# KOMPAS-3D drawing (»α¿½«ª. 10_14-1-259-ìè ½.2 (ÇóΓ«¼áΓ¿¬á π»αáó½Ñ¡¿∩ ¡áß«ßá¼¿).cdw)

Views: Вид 1
Referenced files in C:\Users\РЗА Елена\Desktop\: Библиотека РЗА.lfr|02 - Вторичные цепи|Контакты|Контакт 01, Библиотека РЗА.lfr, Библиотека РЗА.lfr|02 - Вторичные цепи|Клеммы, перемычки, соединения|01-Клемма
Referenced files in C:\Program Files\ASCON\KOMPAS-3D V10\Libs\: Библиотека РЗА.lfr
Referenced files in X:\Проекты\ПС 110 кВ Северные ЭС\5. ПС Опорная\2. Проект\04-РЗА\Рабочая документация\022-УА\: 1014-1-022-УА (Телеизмерения 110 кВ).cdw
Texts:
  РЗА Роман
  Текст на чертеже
  Размерные надписи
  Шероховатость
  Линия-выноска #1
  Линия-выноска #2
  Линия-выноска #3
  Отклонения формы и база
  Заголовок таблицы
  Ячейка таблицы
  Стрелка вида
  Обозначение изменения
  Фигурная скобка
  Номер узла
  Марка координационной оси
  VRCB
  Выносная надпись
  Обозначение узла
  Марка/позиционное обозначение с линией-выноской
  Марка/позиционное обозначение на линии
  Марка/позиционное обозначение без линии-выноски
  02 - Вторичные цепи|Контакты|Контакт 01
  02 - Вторичные цепи|Клеммы, перемычки, соединения|01-Клемма
  CONTINUOUS0
  Стили документа
  Без имени
  Additional DXF text style 0
  Лит-Масса-Масштаб
  Материал-Предприятие
  Normal
  Обычный
  Термин
  Список определений
  Адрес
  Цитаты
  Форматированный
  Courier New
  Z-конец формы
  Z-начало формы
  Title Specification
  Body Specification ( left align )
  Body Specificaton ( centered )
  Body Text
  цепи
  ссылки
  табл
  Подпись в квадратике
  Тексты. 3,2
  ЗОНА_привяз
  heading 1
  Знак Знак Знак Знак Знак Знак
  Verdana
  Body Text 3
  Title
  текст переноса
  ТекстШаг1
  Маркировка
  клеммы, контакты
  тексты табл
  ООббыыччнныыйй
  ТТееррммиинн
  ССппииссоокк ооппррееддееллеенниийй
  ААддрреесс
  ЦЦииттааттыы
  ФФооррммааттиирроовваанннныыйй
  Z-ккооннеецц ффооррммыы
  Z-ннааччааллоо ффооррммыы
  Simplex
  Txt
  MS Sans Serif
  heading 2
  AGOpus
  footer
  russ
  Аппараты
  подписи
  txt
  style2
  Definition Term
  Definition List
  Address
  Blockquote
  Preformatted
  z-Bottom of Form
  z-Top of Form
  TXT
  Абзац Знак
  Шрифт 2.5
  Заголовки
  Table Contents
  Table Heading
  Денис
  header
  HeliosLight
  Pa3
  Pa1
  heading 8
  heading 3
  heading 6
  heading 7
  heading 4
  heading 5
  heading 9
  ГОСТ_МНЕ
  ESK - Обозначение
  GOST 2.304 type A
  rustxt
  RUSTXT
  маркировка
  Состав чартежа
  ячейка табл.
  Tahoma
  Ссылки
  Пояснения
  Клеммник текст
  Текст 3,5
  .07 RGB_0_0_0 i0b0u0
  ISOCP
  CM12
  romans
  текст табл
  Body Text Indent 3
  Основной текст с отступом 3
  терминал
  Перечень элементов
  Поз.
  обозначение
  Кол.
  KSL1, KSL2
  Датчик реле-уровня жидкости
  см.п.п. 3
  Примечания:
  Разводка кабеля силовой и осветительной сети очистной установки включить в поставку
  завода-изготовителя.
  Сигнал "Вызов к шкафу автоматики управления насосами" включает:
  - аварийное отключение автоматических включателей, установленных в шкафу автоматики;
  - неисправность автоматики управления насосами;
  - останов насоса при высоком уровне воды в резервуаре или срабатывании РЗА.
  3. Тип датчика реле-уровня жидкости определяет завод изготовитель. Комплектно с датчиками включить
  в поставку сигнальные электроды рассчитанные на глубину погружения 3200 мм в маслосборник.
  Шкаф
  автоматики
  управления
  насосами
  Маслосборник
  KSL1
  Пуск двигателя
  насоса
  (высокий уровень
  воды в
  маслосборнике)
  Останов
  двигателя
  насоса (высокий
  уровень воды в
  резервуаре)
  насоса при
  срабатывании
  основных защит
  трансформаторов
  Резервуар
  KSL2
  Защита тр-ра 1Т
  Центральная
  сигнализация
  К цепям переменного тока 380 В, 50 Гц
  (основной источник питания)
  (резервный источник питания)
  Шкаф автоматики и управления
  Двигатель
  насосов
  Высокий уровень
  маслосборнике
  Вызов к шкафу
  (см. п.п 2)
  Цепи питания
  Внешние цепи шкафа
  Электрообогрев
  Освещение
  См. п.п. 1
  Защита тр-ра 2Т
  осн 2
  Толщина 0,5
  CONTINUOUS_RGB_0_0_0_THICK_0.18
  Реконструкция ПС 110 кВ Опорная
  (замена трансформаторов 16МВА на 40МВА)
  Автоматика управления насосами.
  Схема электрическая принципиальная
  Разраб.
  Алдошина
  Симакова
  Н.контр.
Dimensions and other numbers on the sheet: 10/14-1-259-НК; 7; 3,2 (надписи); 2,5; 3,2_; 3,2; 3,5; 2,5_3; 5_заголовок; 2,5_01; 2,5 (контакты, клеммы); 2,3_; 2,5 грязносинь; 3,2_зона не привяз; 2.5; 3,5_01; 3,5_tabl; 1,8; 3.5; 5; 3,2 элементы; 3,2 линия; 3,2 таблица; 3.2 маркировка; 2.5_Э5_надписи; 2.5_Э5_ссылки; 2.5_кабель; 3.2; 2.5 надписи; 3,2 (Зоны); 3.2 (текст); 2.5 курсив; 5,0_белый_подчёркнутый; 3.2 фиол; 0 i0b0u0; 2; 1Т, 2Т; 0.5; 11.12; 10/14-1-022-УА-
